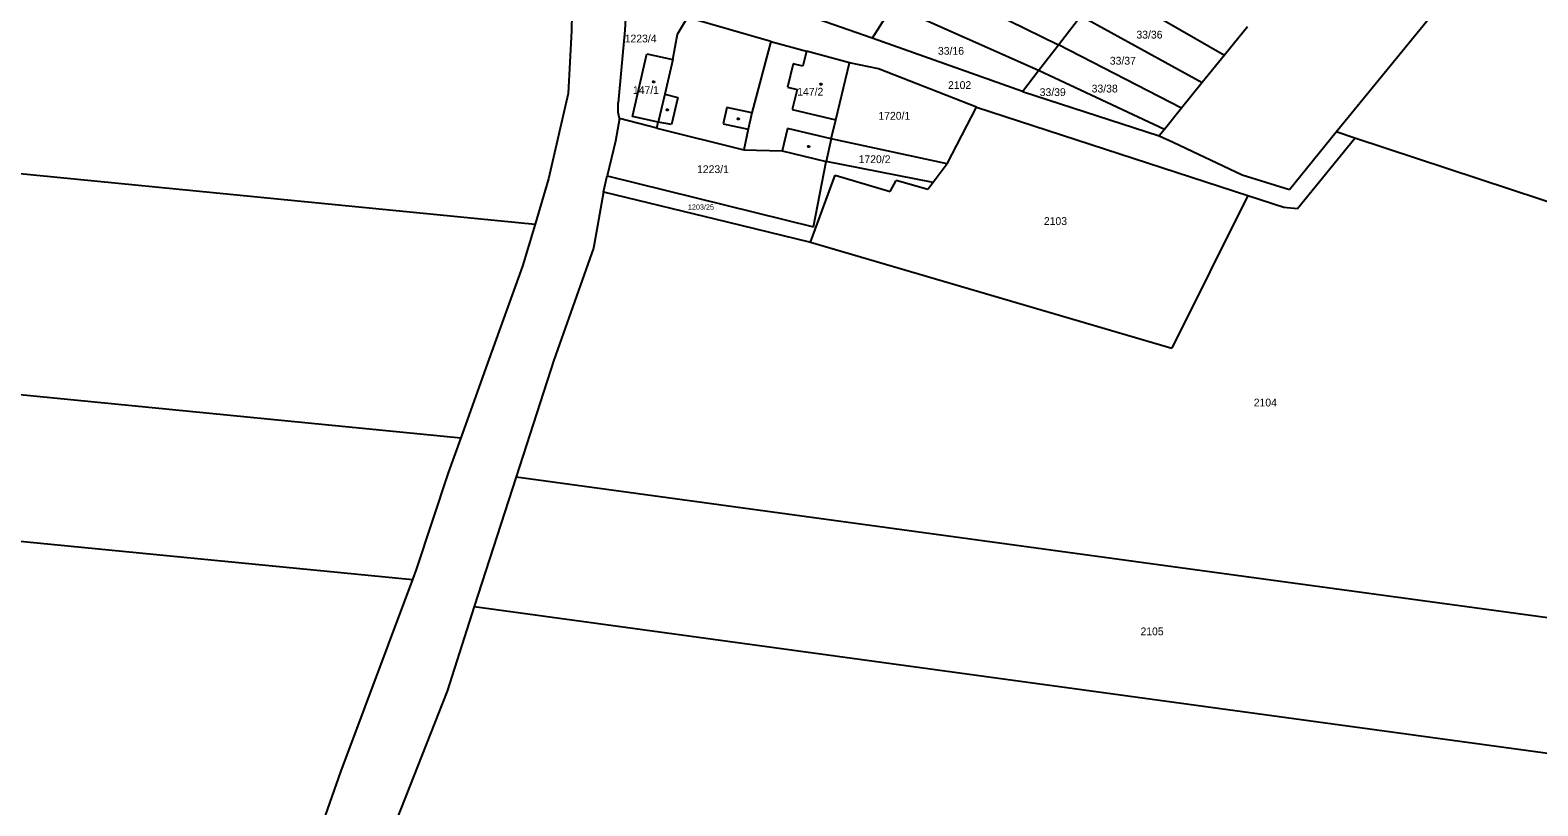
# Model space of a CAD drawing. Extents: x -802857 to -799647, y -1020285 to -1015884.
# Drawn here: x -801830.8 to -801501.8, y -1018091.1 to -1017921.9 of the extents above; entities that cross this region are included whole.
import ezdxf

# ---------------------------------------------------------------- set-up
doc = ezdxf.new("R2010")
doc.units = 0
for name, color, linetype in [('Default', 7, 'Continuous'), ('KN_HRANICE', 7, 'Continuous'), ('KN_KULTURY', 7, 'Continuous'), ('KN_PARCELY', 7, 'Continuous'), ('KN_SLUCKY', 7, 'Continuous')]:
    doc.layers.add(name, color=color, linetype=linetype)

# ---------------------------------------------------------------- blocks, each defined once
blk = doc.blocks.new('402')
at = {"layer": 'Default'}
blk.add_lwpolyline([(0.09, 0.15), (0.18, 0), (0.09, -0.15), (-0.09, -0.15), (-0.18, 0), (-0.09, 0.15), (0.09, 0.15)], dxfattribs=at)

msp = doc.modelspace()

# ---------------------------------------------------------------- linework, layer by layer
at = {"layer": 'KN_HRANICE'}
for p, q in [((-801712.25, -1017904.5), (-801712.72, -1017922.03)), ((-801545.79, -1017944.12), (-801514.75, -1017906.05)), ((-801638, -1017909.59), (-801606.41, -1017925.09)), ((-801596.46, -1017912.23), (-801570.17, -1017927.35)), ((-801700.71, -1017915.44), (-801701.04, -1017921.92)), ((-801642.56, -1017916.61), (-801647.06, -1017923.69)), ((-801610.75, -1017930.7), (-801642.56, -1017916.61)), ((-801689.53, -1017922.82), (-801687.37, -1017919.18)), ((-801669.21, -1017924.37), (-801687.37, -1017919.18)), ((-801647.06, -1017923.69), (-801659, -1017919.5)), ((-801606.41, -1017925.09), (-801601.56, -1017918.81)), ((-801601.56, -1017918.81), (-801575.03, -1017933.33)), ((-801712.72, -1017922.03), (-801713.41, -1017935.69)), ((-801701.04, -1017921.92), (-801702.5, -1017937.79)), ((-801690.54, -1017928.32), (-801689.53, -1017922.82)), ((-801614.29, -1017935.28), (-801647.06, -1017923.69)), ((-801565.18, -1017921.19), (-801570.17, -1017927.35)), ((-801699.38, -1017940.73), (-801696.22, -1017927.05)), ((-801696.22, -1017927.05), (-801690.54, -1017928.32)), ((-801669.21, -1017924.37), (-801673.31, -1017939.96)), ((-801669.21, -1017924.37), (-801664.61, -1017925.62)), ((-801664.61, -1017925.62), (-801661.38, -1017926.49)), ((-801652.01, -1017929.02), (-801661.38, -1017926.49)), ((-801610.75, -1017930.7), (-801606.41, -1017925.09)), ((-801579.54, -1017938.9), (-801606.41, -1017925.09)), ((-801655, -1017941.44), (-801652.01, -1017929.02)), ((-801645.7, -1017930.31), (-801652.01, -1017929.02)), ((-801624.34, -1017938.67), (-801645.7, -1017930.31)), ((-801570.17, -1017927.35), (-801575.03, -1017933.33)), ((-801614.29, -1017935.28), (-801610.75, -1017930.7)), ((-801583.31, -1017943.56), (-801610.75, -1017930.7)), ((-801575.03, -1017933.33), (-801579.54, -1017938.9)), ((-801713.41, -1017935.69), (-801717.68, -1017954.3)), ((-801614.29, -1017935.28), (-801584.43, -1017944.94)), ((-801702.53, -1017939.9), (-801702.5, -1017937.79)), ((-801702.23, -1017941.16), (-801702.53, -1017939.9)), ((-801673.31, -1017939.96), (-801674.1, -1017943.47)), ((-801630.72, -1017951.07), (-801624.34, -1017938.67)), ((-801624.34, -1017938.67), (-801565.08, -1017957.94)), ((-801579.54, -1017938.9), (-801583.31, -1017943.56)), ((-801702.23, -1017941.16), (-801703.11, -1017946.14)), ((-801694.06, -1017943.32), (-801702.23, -1017941.16)), ((-801693.74, -1017941.99), (-801699.38, -1017940.73)), ((-801694.06, -1017943.32), (-801693.74, -1017941.99)), ((-801694.06, -1017943.32), (-801675.09, -1017948.01)), ((-801674.1, -1017943.47), (-801675.09, -1017948.01)), ((-801656, -1017945.61), (-801655, -1017941.44)), ((-801583.31, -1017943.56), (-801584.43, -1017944.94)), ((-801703.11, -1017946.14), (-801704.9, -1017953.69)), ((-801656, -1017945.61), (-801657.1, -1017950.52)), ((-801630.72, -1017951.07), (-801656, -1017945.61)), ((-801584.43, -1017944.94), (-801581.41, -1017946.37)), ((-801581.41, -1017946.37), (-801566.32, -1017953.49)), ((-801556.03, -1017956.68), (-801545.79, -1017944.12)), ((-801554.26, -1017960.84), (-801541.72, -1017945.47)), ((-801541.72, -1017945.47), (-801545.79, -1017944.12)), ((-801463.32, -1017971.38), (-801541.72, -1017945.47)), ((-801675.09, -1017948.01), (-801666.69, -1017948.26)), ((-801666.69, -1017948.26), (-801657.1, -1017950.52)), ((-801842.31, -1017952.29), (-801720.64, -1017964.21)), ((-801660.51, -1017968.18), (-801655.15, -1017953.56)), ((-801659.86, -1017964.81), (-801657.1, -1017950.52)), ((-801633.78, -1017955.15), (-801657.1, -1017950.52)), ((-801655.15, -1017953.56), (-801643.16, -1017957.11)), ((-801630.72, -1017951.07), (-801633.78, -1017955.15)), ((-801566.32, -1017953.49), (-801556.03, -1017956.68)), ((-801717.68, -1017954.3), (-801720.64, -1017964.21)), ((-801705.73, -1017957.16), (-801704.9, -1017953.69)), ((-801704.9, -1017953.69), (-801659.86, -1017964.81)), ((-801643.16, -1017957.11), (-801641.86, -1017954.69)), ((-801634.9, -1017956.64), (-801641.86, -1017954.69)), ((-801633.78, -1017955.15), (-801634.9, -1017956.64)), ((-801705.73, -1017957.16), (-801707.04, -1017964.62)), ((-801705.73, -1017957.16), (-801678.7, -1017963.69)), ((-801565.08, -1017957.94), (-801581.66, -1017991.28)), ((-801565.08, -1017957.94), (-801557.21, -1017960.5)), ((-801557.21, -1017960.5), (-801554.26, -1017960.84)), ((-801720.64, -1017964.21), (-801723.37, -1017973.37)), ((-801707.04, -1017964.62), (-801707.88, -1017969.44)), ((-801678.7, -1017963.69), (-801660.51, -1017968.18)), ((-801707.88, -1017969.44), (-801716.57, -1017993.91)), ((-801660.51, -1017968.18), (-801635.73, -1017975.44)), ((-801723.37, -1017973.37), (-801730.7, -1017993.71)), ((-801635.73, -1017975.44), (-801581.66, -1017991.28)), ((-801730.7, -1017993.71), (-801736.86, -1018010.79)), ((-801716.57, -1017993.91), (-801724.75, -1018019.29)), ((-801847.73, -1017999.9), (-801736.86, -1018010.79)), ((-801736.86, -1018010.79), (-801739.61, -1018018.43)), ((-801739.61, -1018018.43), (-801746.57, -1018039.5)), ((-801724.75, -1018019.29), (-801733.89, -1018047.63)), ((-801724.75, -1018019.29), (-801581.46, -1018038.85)), ((-801861.32, -1018030.55), (-801747.41, -1018041.74)), ((-801581.46, -1018038.85), (-801426.55, -1018059.97)), ((-801747.41, -1018041.74), (-801763.06, -1018083.68)), ((-801746.57, -1018039.5), (-801747.41, -1018041.74)), ((-801733.89, -1018047.63), (-801739.83, -1018066.05)), ((-801733.89, -1018047.63), (-801585.98, -1018067.8)), ((-801739.83, -1018066.05), (-801758.43, -1018113.29)), ((-801585.98, -1018067.8), (-801433.15, -1018088.64)), ((-801763.06, -1018083.68), (-801775.25, -1018117.88))]:
    msp.add_line(p, q, dxfattribs=at)
at = {"layer": 'KN_SLUCKY'}
for p, q in [((-801661.38, -1017926.49), (-801662.17, -1017929.76)), ((-801690.54, -1017928.32), (-801692.31, -1017935.88)), ((-801664.32, -1017929.24), (-801665.56, -1017934.35)), ((-801662.17, -1017929.76), (-801664.32, -1017929.24)), ((-801692.31, -1017935.88), (-801693.74, -1017941.99)), ((-801692.31, -1017935.88), (-801689.46, -1017936.58)), ((-801689.46, -1017936.58), (-801690.85, -1017942.51)), ((-801665.56, -1017934.35), (-801663.44, -1017934.88)), ((-801663.44, -1017934.88), (-801664.52, -1017939.23)), ((-801678.79, -1017938.79), (-801679.57, -1017942.35)), ((-801673.31, -1017939.96), (-801678.79, -1017938.79)), ((-801664.52, -1017939.23), (-801655, -1017941.44)), ((-801690.85, -1017942.51), (-801693.74, -1017941.99)), ((-801679.57, -1017942.35), (-801674.1, -1017943.47)), ((-801665.56, -1017943.39), (-801666.69, -1017948.26)), ((-801656, -1017945.61), (-801665.56, -1017943.39))]:
    msp.add_line(p, q, dxfattribs=at)

# ---------------------------------------------------------------- block references
at = {"layer": 'KN_KULTURY'}
for p in [(-801694.74, -1017933.18), (-801658.25, -1017933.68), (-801691.76, -1017939.27), (-801676.29, -1017941.22), (-801660.92, -1017947.29)]:
    msp.add_blockref('402', p, dxfattribs=at)

# ---------------------------------------------------------------- texts
at = {"layer": 'KN_PARCELY'}
for s, height, p in [('1223/4', 1.7, (-801701.08, -1017924.59)), ('33/36', 1.7, (-801589.41, -1017923.74)), ('33/16', 1.7, (-801632.72, -1017927.27)), ('33/37', 1.7, (-801595.22, -1017929.43)), ('2102', 1.7, (-801630.52, -1017934.74)), ('33/38', 1.7, (-801599.18, -1017935.5)), ('147/1', 1.7, (-801699.28, -1017935.83)), ('147/2', 1.7, (-801663.43, -1017936.19)), ('33/39', 1.7, (-801610.52, -1017936.28)), ('1720/1', 1.7, (-801645.72, -1017941.44)), ('1720/2', 1.7, (-801650.03, -1017950.91)), ('1223/1', 1.7, (-801685.29, -1017953.08)), ('1203/25', 1.14, (-801687.29, -1017961.07)), ('2103', 1.7, (-801609.61, -1017964.4)), ('2104', 1.7, (-801563.81, -1018003.98)), ('2105', 1.7, (-801588.53, -1018053.88))]:
    msp.add_text(s, height=height, dxfattribs=at).set_placement(p)

doc.saveas('drawing.dxf')
